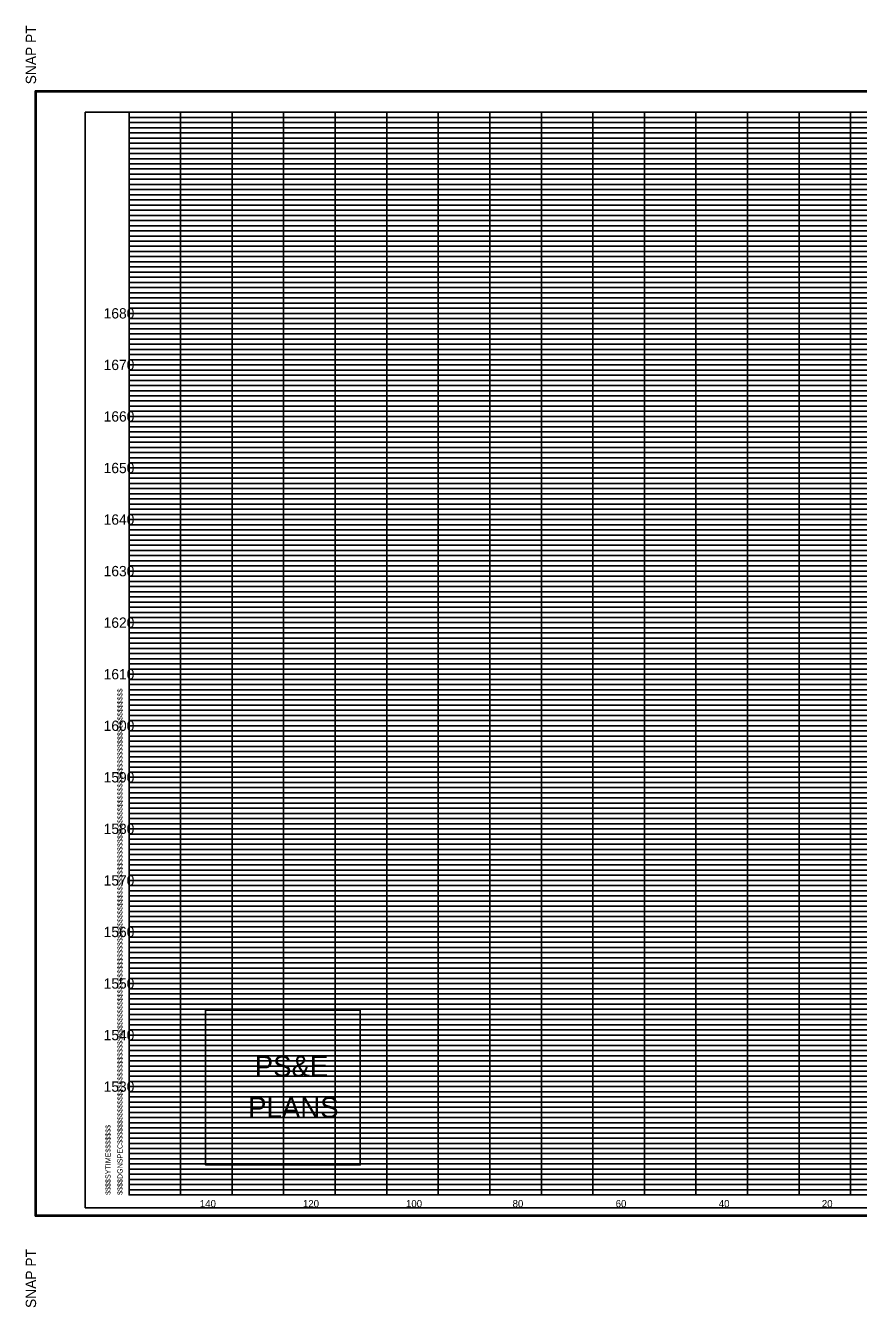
# Model space of a CAD drawing. Extents: x 980 to 1380, y 1248 to 3387.
# Drawn here: x 979.9 to 1141.5, y 1518.2 to 1766.8 of the extents above; entities that cross this region are included whole.
import ezdxf

# ---------------------------------------------------------------- set-up
doc = ezdxf.new("R2010")
doc.units = 0
for name, color, linetype in [('DESIGN - SHEET - Corner Text', 7, 'Continuous'), ('DESIGN - SHEET - Light Grid', 7, 'Continuous'), ('DESIGN - SHEET - Linework', 7, 'Continuous'), ('DESIGN - SHEET - Plot Shape', 7, 'Continuous'), ('DESIGN - TYPICAL - Text', 7, 'Continuous')]:
    doc.layers.add(name, color=color, linetype=linetype)

# ---------------------------------------------------------------- blocks, each defined once
blk = doc.blocks.new('XSTSHT')
at = {"layer": 'DESIGN - SHEET - Light Grid'}
for p, q in [((0, 20.9), (8, 20.9)), ((8, 20.9), (16, 20.9)), ((0, 20.8), (8, 20.8)), ((0, 20.7), (8, 20.7)), ((8, 20.8), (16, 20.8)), ((8, 20.7), (16, 20.7)), ((0, 20.6), (8, 20.6)), ((0, 20.5), (8, 20.5)), ((0, 20.4), (8, 20.4)), ((8, 20.6), (16, 20.6)), ((8, 20.5), (16, 20.5)), ((8, 20.4), (16, 20.4)), ((0, 20.3), (8, 20.3)), ((0, 20.2), (8, 20.2)), ((8, 20.3), (16, 20.3)), ((8, 20.2), (16, 20.2)), ((0, 20.1), (8, 20.1)), ((0, 19.9), (8, 19.9)), ((8, 20.1), (16, 20.1)), ((8, 19.9), (16, 19.9)), ((0, 19.8), (8, 19.8)), ((0, 19.7), (8, 19.7)), ((8, 19.8), (16, 19.8)), ((8, 19.7), (16, 19.7)), ((0, 19.6), (8, 19.6)), ((0, 19.5), (8, 19.5)), ((0, 19.4), (8, 19.4)), ((8, 19.6), (16, 19.6)), ((8, 19.5), (16, 19.5)), ((8, 19.4), (16, 19.4)), ((0, 19.3), (8, 19.3)), ((0, 19.2), (8, 19.2)), ((8, 19.3), (16, 19.3)), ((8, 19.2), (16, 19.2)), ((0, 19.1), (8, 19.1)), ((0, 18.9), (8, 18.9)), ((8, 19.1), (16, 19.1)), ((8, 18.9), (16, 18.9)), ((0, 18.8), (8, 18.8)), ((0, 18.7), (8, 18.7)), ((8, 18.8), (16, 18.8)), ((8, 18.7), (16, 18.7)), ((0, 18.6), (8, 18.6)), ((0, 18.5), (8, 18.5)), ((0, 18.4), (8, 18.4)), ((8, 18.6), (16, 18.6)), ((8, 18.5), (16, 18.5)), ((8, 18.4), (16, 18.4)), ((0, 18.3), (8, 18.3)), ((0, 18.2), (8, 18.2)), ((8, 18.3), (16, 18.3)), ((8, 18.2), (16, 18.2)), ((0, 18.1), (8, 18.1)), ((8, 18.1), (16, 18.1)), ((0, 17.9), (8, 17.9)), ((0, 17.8), (8, 17.8)), ((0, 17.7), (8, 17.7)), ((8, 17.9), (16, 17.9)), ((8, 17.8), (16, 17.8)), ((8, 17.7), (16, 17.7)), ((0, 17.6), (8, 17.6)), ((0, 17.5), (8, 17.5)), ((8, 17.6), (16, 17.6)), ((8, 17.5), (16, 17.5)), ((0, 17.4), (8, 17.4)), ((0, 17.3), (8, 17.3)), ((0, 17.2), (8, 17.2)), ((8, 17.4), (16, 17.4)), ((8, 17.3), (16, 17.3)), ((8, 17.2), (16, 17.2)), ((0, 17.1), (8, 17.1)), ((8, 17.1), (16, 17.1)), ((0, 16.9), (8, 16.9)), ((0, 16.8), (8, 16.8)), ((0, 16.7), (8, 16.7)), ((8, 16.9), (16, 16.9)), ((8, 16.8), (16, 16.8)), ((8, 16.7), (16, 16.7)), ((0, 16.6), (8, 16.6)), ((0, 16.5), (8, 16.5)), ((8, 16.6), (16, 16.6)), ((8, 16.5), (16, 16.5)), ((0, 16.4), (8, 16.4)), ((0, 16.3), (8, 16.3)), ((0, 16.2), (8, 16.2)), ((8, 16.4), (16, 16.4)), ((8, 16.3), (16, 16.3)), ((8, 16.2), (16, 16.2)), ((0, 16.1), (8, 16.1)), ((8, 16.1), (16, 16.1)), ((0, 15.9), (8, 15.9)), ((0, 15.8), (8, 15.8)), ((0, 15.7), (8, 15.7)), ((8, 15.9), (16, 15.9)), ((8, 15.8), (16, 15.8)), ((8, 15.7), (16, 15.7)), ((0, 15.6), (8, 15.6)), ((0, 15.5), (8, 15.5)), ((8, 15.6), (16, 15.6)), ((8, 15.5), (16, 15.5)), ((0, 15.4), (8, 15.4)), ((0, 15.3), (8, 15.3)), ((0, 15.2), (8, 15.2)), ((8, 15.4), (16, 15.4)), ((8, 15.3), (16, 15.3)), ((8, 15.2), (16, 15.2)), ((0, 15.1), (8, 15.1)), ((8, 15.1), (16, 15.1)), ((0, 14.9), (8, 14.9)), ((0, 14.8), (8, 14.8)), ((0, 14.7), (8, 14.7)), ((8, 14.9), (16, 14.9)), ((8, 14.8), (16, 14.8)), ((8, 14.7), (16, 14.7)), ((0, 14.6), (8, 14.6)), ((0, 14.5), (8, 14.5)), ((8, 14.6), (16, 14.6)), ((8, 14.5), (16, 14.5)), ((0, 14.4), (8, 14.4)), ((0, 14.3), (8, 14.3)), ((0, 14.2), (8, 14.2)), ((8, 14.4), (16, 14.4)), ((8, 14.3), (16, 14.3)), ((8, 14.2), (16, 14.2)), ((0, 14.1), (8, 14.1)), ((8, 14.1), (16, 14.1)), ((0, 13.9), (8, 13.9)), ((0, 13.8), (8, 13.8)), ((0, 13.7), (8, 13.7)), ((8, 13.9), (16, 13.9)), ((8, 13.8), (16, 13.8)), ((8, 13.7), (16, 13.7)), ((0, 13.6), (8, 13.6)), ((0, 13.5), (8, 13.5)), ((8, 13.6), (16, 13.6)), ((8, 13.5), (16, 13.5)), ((0, 13.4), (8, 13.4)), ((0, 13.3), (8, 13.3)), ((0, 13.2), (8, 13.2)), ((8, 13.4), (16, 13.4)), ((8, 13.3), (16, 13.3)), ((8, 13.2), (16, 13.2)), ((0, 13.1), (8, 13.1)), ((8, 13.1), (16, 13.1)), ((0, 12.9), (8, 12.9)), ((0, 12.8), (8, 12.8)), ((0, 12.7), (8, 12.7)), ((8, 12.9), (16, 12.9)), ((8, 12.8), (16, 12.8)), ((8, 12.7), (16, 12.7)), ((0, 12.6), (8, 12.6)), ((0, 12.5), (8, 12.5)), ((8, 12.6), (16, 12.6)), ((8, 12.5), (16, 12.5)), ((0, 12.4), (8, 12.4)), ((0, 12.3), (8, 12.3)), ((0, 12.2), (8, 12.2)), ((8, 12.4), (16, 12.4)), ((8, 12.3), (16, 12.3)), ((8, 12.2), (16, 12.2)), ((0, 12.1), (8, 12.1)), ((8, 12.1), (16, 12.1)), ((0, 11.9), (8, 11.9)), ((0, 11.8), (8, 11.8)), ((0, 11.7), (8, 11.7)), ((8, 11.9), (16, 11.9)), ((8, 11.8), (16, 11.8)), ((8, 11.7), (16, 11.7)), ((0, 11.6), (8, 11.6)), ((0, 11.5), (8, 11.5)), ((8, 11.6), (16, 11.6)), ((8, 11.5), (16, 11.5)), ((0, 11.4), (8, 11.4)), ((0, 11.3), (8, 11.3)), ((0, 11.2), (8, 11.2)), ((8, 11.4), (16, 11.4)), ((8, 11.3), (16, 11.3)), ((8, 11.2), (16, 11.2)), ((0, 11.1), (8, 11.1)), ((8, 11.1), (16, 11.1)), ((0, 10.9), (8, 10.9)), ((0, 10.8), (8, 10.8)), ((0, 10.7), (8, 10.7)), ((8, 10.9), (16, 10.9)), ((8, 10.8), (16, 10.8)), ((8, 10.7), (16, 10.7)), ((0, 10.6), (8, 10.6)), ((0, 10.5), (8, 10.5)), ((8, 10.6), (16, 10.6)), ((8, 10.5), (16, 10.5)), ((0, 10.4), (8, 10.4)), ((0, 10.3), (8, 10.3)), ((0, 10.2), (8, 10.2)), ((8, 10.4), (16, 10.4)), ((8, 10.3), (16, 10.3)), ((8, 10.2), (16, 10.2)), ((0, 10.1), (8, 10.1)), ((8, 10.1), (16, 10.1)), ((0, 9.9), (8, 9.9)), ((0, 9.8), (8, 9.8)), ((0, 9.7), (8, 9.7)), ((8, 9.9), (16, 9.9)), ((8, 9.8), (16, 9.8)), ((8, 9.7), (16, 9.7)), ((0, 9.6), (8, 9.6)), ((0, 9.5), (8, 9.5)), ((8, 9.6), (16, 9.6)), ((8, 9.5), (16, 9.5)), ((0, 9.4), (8, 9.4)), ((0, 9.3), (8, 9.3)), ((0, 9.2), (8, 9.2)), ((8, 9.4), (16, 9.4)), ((8, 9.3), (16, 9.3)), ((8, 9.2), (16, 9.2)), ((0, 9.1), (8, 9.1)), ((8, 9.1), (16, 9.1)), ((0, 8.9), (8, 8.9)), ((0, 8.8), (8, 8.8)), ((8, 8.9), (16, 8.9)), ((8, 8.8), (16, 8.8)), ((0, 8.7), (8, 8.7)), ((0, 8.6), (8, 8.6)), ((0, 8.5), (8, 8.5)), ((8, 8.7), (16, 8.7)), ((8, 8.6), (16, 8.6)), ((8, 8.5), (16, 8.5)), ((0, 8.4), (8, 8.4)), ((0, 8.3), (8, 8.3)), ((8, 8.4), (16, 8.4)), ((8, 8.3), (16, 8.3)), ((0, 8.2), (8, 8.2)), ((0, 8.1), (8, 8.1)), ((8, 8.2), (16, 8.2)), ((8, 8.1), (16, 8.1)), ((0, 7.9), (8, 7.9)), ((0, 7.8), (8, 7.8)), ((8, 7.9), (16, 7.9)), ((8, 7.8), (16, 7.8)), ((0, 7.7), (8, 7.7)), ((0, 7.6), (8, 7.6)), ((0, 7.5), (8, 7.5)), ((8, 7.7), (16, 7.7)), ((8, 7.6), (16, 7.6)), ((8, 7.5), (16, 7.5)), ((0, 7.4), (8, 7.4)), ((0, 7.3), (8, 7.3)), ((8, 7.4), (16, 7.4)), ((8, 7.3), (16, 7.3)), ((0, 7.2), (8, 7.2)), ((0, 7.1), (8, 7.1)), ((8, 7.2), (16, 7.2)), ((8, 7.1), (16, 7.1)), ((0, 6.9), (8, 6.9)), ((0, 6.8), (8, 6.8)), ((8, 6.9), (16, 6.9)), ((8, 6.8), (16, 6.8)), ((0, 6.7), (8, 6.7)), ((0, 6.6), (8, 6.6)), ((0, 6.5), (8, 6.5)), ((8, 6.7), (16, 6.7)), ((8, 6.6), (16, 6.6)), ((8, 6.5), (16, 6.5)), ((0, 6.4), (8, 6.4)), ((0, 6.3), (8, 6.3)), ((8, 6.4), (16, 6.4)), ((8, 6.3), (16, 6.3)), ((0, 6.2), (8, 6.2)), ((0, 6.1), (8, 6.1)), ((8, 6.2), (16, 6.2)), ((8, 6.1), (16, 6.1)), ((0, 5.9), (8, 5.9)), ((0, 5.8), (8, 5.8)), ((8, 5.9), (16, 5.9)), ((8, 5.8), (16, 5.8)), ((0, 5.7), (8, 5.7)), ((0, 5.6), (8, 5.6)), ((0, 5.5), (8, 5.5)), ((8, 5.7), (16, 5.7)), ((8, 5.6), (16, 5.6)), ((8, 5.5), (16, 5.5)), ((0, 5.4), (8, 5.4)), ((0, 5.3), (8, 5.3)), ((8, 5.4), (16, 5.4)), ((8, 5.3), (16, 5.3)), ((0, 5.2), (8, 5.2)), ((0, 5.1), (8, 5.1)), ((8, 5.2), (16, 5.2)), ((8, 5.1), (16, 5.1)), ((0, 4.9), (8, 4.9)), ((0, 4.8), (8, 4.8)), ((8, 4.9), (16, 4.9)), ((8, 4.8), (16, 4.8)), ((0, 4.7), (8, 4.7)), ((0, 4.6), (8, 4.6)), ((0, 4.5), (8, 4.5)), ((8, 4.7), (16, 4.7)), ((8, 4.6), (16, 4.6)), ((8, 4.5), (16, 4.5)), ((0, 4.4), (8, 4.4)), ((0, 4.3), (8, 4.3)), ((8, 4.4), (16, 4.4)), ((8, 4.3), (16, 4.3)), ((0, 4.2), (8, 4.2)), ((0, 4.1), (8, 4.1)), ((8, 4.2), (16, 4.2)), ((8, 4.1), (16, 4.1)), ((0, 3.9), (8, 3.9)), ((0, 3.8), (8, 3.8)), ((8, 3.9), (16, 3.9)), ((8, 3.8), (16, 3.8)), ((0, 3.7), (8, 3.7)), ((0, 3.6), (8, 3.6)), ((0, 3.5), (8, 3.5)), ((8, 3.7), (16, 3.7)), ((8, 3.6), (16, 3.6)), ((8, 3.5), (16, 3.5)), ((0, 3.4), (8, 3.4)), ((0, 3.3), (8, 3.3)), ((8, 3.4), (16, 3.4)), ((8, 3.3), (16, 3.3)), ((0, 3.2), (8, 3.2)), ((0, 3.1), (8, 3.1)), ((8, 3.2), (16, 3.2)), ((8, 3.1), (16, 3.1)), ((0, 2.9), (8, 2.9)), ((0, 2.8), (8, 2.8)), ((8, 2.9), (16, 2.9)), ((8, 2.8), (16, 2.8)), ((0, 2.7), (8, 2.7)), ((0, 2.6), (8, 2.6)), ((0, 2.5), (8, 2.5)), ((8, 2.7), (16, 2.7)), ((8, 2.6), (16, 2.6)), ((8, 2.5), (16, 2.5)), ((0, 2.4), (8, 2.4)), ((0, 2.3), (8, 2.3)), ((8, 2.4), (16, 2.4)), ((8, 2.3), (16, 2.3)), ((0, 2.2), (8, 2.2)), ((0, 2.1), (8, 2.1)), ((8, 2.2), (16, 2.2)), ((8, 2.1), (16, 2.1)), ((0, 1.9), (8, 1.9)), ((0, 1.8), (8, 1.8)), ((8, 1.9), (16, 1.9)), ((8, 1.8), (16, 1.8)), ((0, 1.7), (8, 1.7)), ((0, 1.6), (8, 1.6)), ((0, 1.5), (8, 1.5)), ((8, 1.7), (16, 1.7)), ((8, 1.6), (16, 1.6)), ((8, 1.5), (16, 1.5)), ((0, 1.4), (8, 1.4)), ((0, 1.3), (8, 1.3)), ((8, 1.4), (16, 1.4)), ((8, 1.3), (16, 1.3)), ((0, 1.2), (8, 1.2)), ((0, 1.1), (8, 1.1)), ((8, 1.2), (16, 1.2)), ((8, 1.1), (16, 1.1)), ((0, 0.9), (8, 0.9)), ((0, 0.8), (8, 0.8)), ((8, 0.9), (16, 0.9)), ((8, 0.8), (16, 0.8)), ((0, 0.7), (8, 0.7)), ((0, 0.6), (8, 0.6)), ((0, 0.5), (8, 0.5)), ((8, 0.7), (16, 0.7)), ((8, 0.6), (16, 0.6)), ((8, 0.5), (16, 0.5)), ((0, 0.4), (8, 0.4)), ((0, 0.3), (8, 0.3)), ((8, 0.4), (16, 0.4)), ((8, 0.3), (16, 0.3)), ((0, 0.2), (8, 0.2)), ((0, 0.1), (8, 0.1)), ((8, 0.2), (16, 0.2)), ((8, 0.1), (16, 0.1))]:
    blk.add_line(p, q, dxfattribs=at)
at = {"layer": 'DESIGN - SHEET - Linework'}
for p, q in [((-1.823, -0.414), (-1.823, 21.414)), ((-1.823, 21.414), (32.217, 21.414)), ((1, 0), (1, 21)), ((2, 0), (2, 21)), ((3, 0), (3, 21)), ((4, 0), (4, 21)), ((5, 0), (5, 21)), ((6, 0), (6, 21)), ((7, 0), (7, 21)), ((8, 0), (8, 21)), ((9, 0), (9, 21)), ((10, 0), (10, 21)), ((11, 0), (11, 21)), ((12, 0), (12, 21)), ((13, 0), (13, 21)), ((14, 0), (14, 21)), ((0, 20), (28, 20)), ((0, 19), (32, 19)), ((0, 18), (32, 18)), ((0, 17), (32, 17)), ((0, 16), (32, 16)), ((0, 15), (32, 15)), ((0, 14), (32, 14)), ((0, 13), (32, 13)), ((0, 12), (32, 12)), ((0, 11), (32, 11)), ((0, 10), (32, 10)), ((0, 9), (32, 9)), ((0, 8), (32, 8)), ((0, 7), (32, 7)), ((0, 6), (32, 6)), ((0, 5), (32, 5)), ((0, 4), (32, 4)), ((0, 3), (32, 3)), ((0, 2), (32, 2)), ((0, 1), (32, 1)), ((-1.823, -0.414), (32.217, -0.414))]:
    blk.add_line(p, q, dxfattribs=at)
blk.add_lwpolyline([(0, 21), (0, 0), (32, 0), (32, 21), (0, 21)], dxfattribs=at)
at = {"layer": 'DESIGN - SHEET - Plot Shape'}
for points in [[(-1.803, 21.394), (32.197, 21.394), (32.197, -0.394), (-1.803, -0.394)], [(-0.85, 21), (32, 21), (32, -0.25), (-0.85, -0.25)]]:
    blk.add_lwpolyline(points, close=True, dxfattribs=at)
at = {"layer": 'DESIGN - SHEET - Corner Text'}
for s, height, p in [('  SNAP PT', 0.2, (-1.803, 21.394)), ('$$$$DGNSPEC$$$$$$$$$$$$$$$$$$$$$$$$$$$$$$$$$$$$$$$$$$$$$$$$$$$$$$$$$$$$$$$$$$$$$$$$$$$$$$$$$$$$$$$$$$$$$$$$$$$$$$$$$$$$$$$$$$$', 0.100002, (-0.126, 0)), ('$$$$SYTIME$$$$$$$', 0.1, (-0.358, 0)), ('SNAP PT  ', 0.2, (-1.803, -2.194))]:
    blk.add_text(s, height=height, rotation=90, dxfattribs=at).set_placement(p)

msp = doc.modelspace()

# ---------------------------------------------------------------- linework, layer by layer
at = {"layer": 'DESIGN - SHEET - Corner Text'}
msp.add_lwpolyline([(1014.87, 1575.8), (1014.87, 1545.8), (1044.87, 1545.8), (1044.87, 1575.8)], close=True, dxfattribs=at)
at = {"layer": 'DESIGN - SHEET - Plot Shape'}
msp.add_lwpolyline([(991.5, 1537.5), (1320, 1537.5), (1320, 1750), (991.5, 1750)], close=True, dxfattribs=at)

# ---------------------------------------------------------------- block references
at = {"layer": 'DESIGN - TYPICAL - Text', "xscale": 10, "yscale": 10}
msp.add_blockref('XSTSHT', (1000, 1540), dxfattribs=at)

# ---------------------------------------------------------------- texts
at = {"layer": 'DESIGN - SHEET - Corner Text'}
for s, p in [('PS&E', (1024.39, 1562.97)), ('PLANS', (1023.11, 1554.97))]:
    msp.add_text(s, height=4, dxfattribs=at).set_placement(p)
at = {"layer": 'DESIGN - TYPICAL - Text'}
for s, height, p in [('     1680     ', 2, (991.37, 1710)), ('     1670     ', 2, (991.37, 1700)), ('     1660     ', 2, (991.37, 1690)), ('     1650     ', 2, (991.37, 1680)), ('     1640     ', 2, (991.37, 1670)), ('     1630     ', 2, (991.37, 1660)), ('     1620     ', 2, (991.37, 1650)), ('     1610     ', 2, (991.37, 1640)), ('     1600     ', 2, (991.37, 1630)), ('     1590     ', 2, (991.37, 1620)), ('     1580     ', 2, (991.37, 1610)), ('     1570     ', 2, (991.37, 1600)), ('     1560     ', 2, (991.37, 1590)), ('     1550     ', 2, (991.37, 1580)), ('     1540     ', 2, (991.37, 1570)), ('     1530     ', 2, (991.37, 1560)), ('     140     ', 1.4, (1011.14, 1537.6)), ('     120     ', 1.4, (1031.14, 1537.6)), ('     100     ', 1.4, (1051.14, 1537.6)), ('     80     ', 1.4, (1071.82, 1537.6)), ('     60     ', 1.4, (1091.82, 1537.6)), ('     40     ', 1.4, (1111.82, 1537.6)), ('     20     ', 1.4, (1131.82, 1537.6))]:
    msp.add_text(s, height=height, dxfattribs=at).set_placement(p)

doc.saveas('drawing.dxf')
